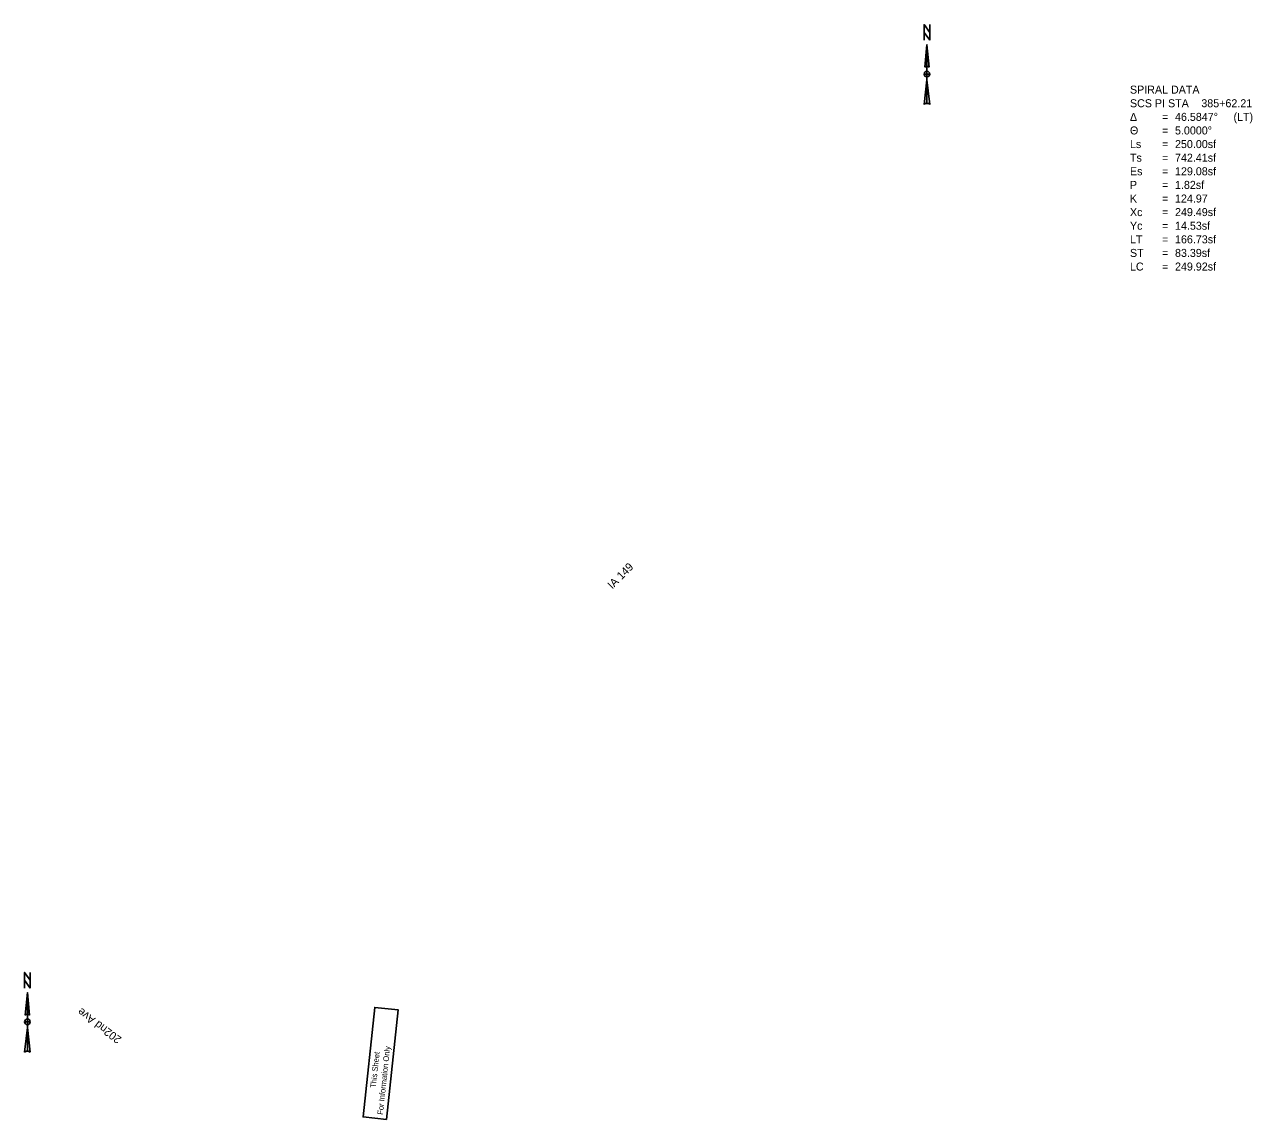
# Model space of a CAD drawing. Extents: x 23417754 to 23421386, y 6737896 to 6790956.
# Drawn here: x 23418102 to 23421177, y 6761524 to 6764265 of the extents above; entities that cross this region are included whole.
import ezdxf

# ---------------------------------------------------------------- set-up
doc = ezdxf.new("R2010")
doc.units = 0
for name, color, linetype in [('Curb', 7, 'Continuous'), ('Default', 7, 'Continuous'), ('RasterAttachment', 7, 'Continuous'), ('TextAlignment', 7, 'Continuous'), ('TextAlignmentLrg', 7, 'Continuous')]:
    doc.layers.add(name, color=color, linetype=linetype)

msp = doc.modelspace()

# ---------------------------------------------------------------- linework, layer by layer
at = {"layer": 'Curb'}
for p, q in [((23418108.9, 6761841.5), (23418114.5, 6761785.2)), ((23418108.9, 6761841.5), (23418108.9, 6761695)), ((23418103.2, 6761785.2), (23418103.2, 6761785.2)), ((23418103.4, 6761785.7), (23418104.5, 6761786.9)), ((23418101.8, 6761692.2), (23418108.9, 6761754.2)), ((23418108.9, 6761761.2), (23418108.9, 6761761.2))]:
    msp.add_line(p, q, dxfattribs=at)
for points in [[(23418115.9, 6761852.8), (23418101.8, 6761872.5), (23418101.8, 6761892.2), (23418115.9, 6761872.5)], [(23418949.3, 6761530.4), (23418978.9, 6761804.4), (23419037.6, 6761798.1), (23419008, 6761524.1)], [(23419008, 6761524.1), (23419037.6, 6761798.1), (23418978.9, 6761804.4), (23418949.3, 6761530.4)]]:
    msp.add_lwpolyline(points, close=True, dxfattribs=at)
for points in [[(23418101.8, 6761852.8), (23418101.8, 6761892.2), (23418115.9, 6761872.5), (23418115.9, 6761892.2)], [(23418103.2, 6761785.2), (23418108.9, 6761841.5), (23418108.9, 6761788)], [(23418108.9, 6761761.2), (23418108.9, 6761768.3), (23418101.8, 6761768.3)], [(23418115.9, 6761768.3), (23418108.9, 6761768.3), (23418108.9, 6761775.3)], [(23418108.9, 6761695), (23418108.9, 6761754.2), (23418115.9, 6761692.2)]]:
    msp.add_lwpolyline(points, dxfattribs=at)
for centre, radius, start, end in [((23418108.9, 6761780.9), 7.04, 90.0204, 143.1257), ((23418108.9, 6761780.9), 7.04, 36.8481, 90.0218), ((23418108.9, 6761768.3), 7.04, 90, 180), ((23418108.9, 6761768.3), 7.04, 180, 270), ((23418108.9, 6761768.3), 7.04, 0, 90), ((23418108.9, 6761768.3), 7.04, 270, 360), ((23418108.9, 6761684.8), 10.2, 89.9894, 133.619), ((23418108.9, 6761684.8), 10.2, 46.4021, 90.0006)]:
    msp.add_arc(centre, radius, start, end, dxfattribs=at)
at = {"layer": 'TextAlignmentLrg'}
for p, q in [((23420361.5, 6764214.5), (23420367.1, 6764158.2)), ((23420361.5, 6764214.5), (23420361.5, 6764068)), ((23420355.8, 6764158.2), (23420355.8, 6764158.2)), ((23420356.1, 6764158.7), (23420357.1, 6764159.9)), ((23420354.4, 6764065.2), (23420361.5, 6764127.2)), ((23420361.5, 6764134.2), (23420361.5, 6764134.2))]:
    msp.add_line(p, q, dxfattribs=at)
msp.add_lwpolyline([(23420368.5, 6764225.8), (23420354.4, 6764245.5), (23420354.4, 6764265.2), (23420368.5, 6764245.5)], close=True, dxfattribs=at)
for points in [[(23420354.4, 6764225.8), (23420354.4, 6764265.2), (23420368.5, 6764245.5), (23420368.5, 6764265.2)], [(23420355.8, 6764158.2), (23420361.5, 6764214.5), (23420361.5, 6764161)], [(23420368.5, 6764141.3), (23420361.5, 6764141.3), (23420361.5, 6764148.3)], [(23420361.5, 6764134.2), (23420361.5, 6764141.3), (23420354.4, 6764141.3)], [(23420361.5, 6764068), (23420361.5, 6764127.2), (23420368.5, 6764065.2)]]:
    msp.add_lwpolyline(points, dxfattribs=at)
for centre, radius, start, end in [((23420361.5, 6764141.3), 7.04, 90, 180), ((23420361.5, 6764154), 7.04, 90.0204, 143.1257), ((23420361.5, 6764154), 7.04, 36.8481, 90.0218), ((23420361.5, 6764141.3), 7.04, 0, 90), ((23420361.5, 6764141.3), 7.04, 180, 270), ((23420361.5, 6764141.3), 7.04, 270, 360), ((23420361.5, 6764057.8), 10.2, 89.9894, 133.619), ((23420361.5, 6764057.8), 10.2, 46.4021, 90.0006)]:
    msp.add_arc(centre, radius, start, end, dxfattribs=at)

# ---------------------------------------------------------------- texts
at = {"layer": 'Curb'}
for s, height, p in [('This Sheet', 14.17, (23418981.4, 6761602.5)), ('For Information Only', 14.174, (23418999.1, 6761535.2))]:
    msp.add_text(s, height=height, rotation=83.835, dxfattribs=at).set_placement(p)
at = {"layer": 'Default'}
msp.add_text('IA 149', height=20, rotation=45.1605, dxfattribs=at).set_placement((23419573.5, 6762850.8))
at = {"layer": 'RasterAttachment'}
msp.add_text('202nd Ave', height=20, rotation=143.2141, dxfattribs=at).set_placement((23418346.2, 6761728.2))
at = {"layer": 'TextAlignment'}
for s, height, p in [('SPIRAL DATA', 20.04, (23420869.8, 6764092.3)), ('SCS PI STA ', 20.04, (23420869.8, 6764058.2)), ('385+62.21', 20.04, (23421048.5, 6764058.2)), ('Δ', 20, (23420869.8, 6764024.1)), ('= ', 20.04, (23420950, 6764024.1)), ('46.5847°', 20.04, (23420982.6, 6764024.1)), (' (LT)', 20.04, (23421121.6, 6764024.1)), ('Θ ', 20.04, (23420869.8, 6763990.1)), ('= ', 20.04, (23420950, 6763990.1)), ('5.0000°', 20.04, (23420982.6, 6763990.1)), ('Ls', 20.04, (23420869.8, 6763956)), ('= ', 20.04, (23420950, 6763956)), ('250.00sf', 20.04, (23420982.6, 6763956)), ('Ts', 20.04, (23420869.8, 6763921.9)), ('= ', 20.04, (23420950, 6763921.9)), ('742.41sf', 20.04, (23420982.6, 6763921.9)), ('Es', 20.04, (23420869.8, 6763887.9)), ('= ', 20.04, (23420950, 6763887.9)), ('129.08sf', 20.04, (23420982.6, 6763887.9)), ('P', 20, (23420869.8, 6763853.8)), ('1.82sf', 20.04, (23420982.6, 6763853.8)), ('= ', 20.04, (23420950, 6763853.8)), ('K', 20, (23420869.8, 6763819.7)), ('= ', 20.04, (23420950, 6763819.7)), ('124.97', 20.04, (23420982.6, 6763819.7)), ('Xc', 20.04, (23420869.8, 6763785.7)), ('= ', 20.04, (23420950, 6763785.7)), ('249.49sf', 20.04, (23420982.6, 6763785.7)), ('Yc', 20.04, (23420869.8, 6763751.6)), ('= ', 20.04, (23420950, 6763751.6)), ('14.53sf', 20.04, (23420982.6, 6763751.6)), ('LT', 20.04, (23420869.8, 6763717.5)), ('= ', 20.04, (23420950, 6763717.5)), ('166.73sf', 20.04, (23420982.6, 6763717.5)), ('ST ', 20.04, (23420869.8, 6763683.5)), ('= ', 20.04, (23420950, 6763683.5)), ('83.39sf', 20.04, (23420982.6, 6763683.5)), ('LC', 20.04, (23420869.8, 6763649.4)), ('= ', 20.04, (23420950, 6763649.4)), ('249.92sf', 20.04, (23420982.6, 6763649.4))]:
    msp.add_text(s, height=height, dxfattribs=at).set_placement(p)

doc.saveas('drawing.dxf')
